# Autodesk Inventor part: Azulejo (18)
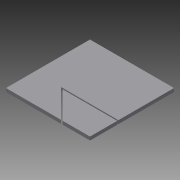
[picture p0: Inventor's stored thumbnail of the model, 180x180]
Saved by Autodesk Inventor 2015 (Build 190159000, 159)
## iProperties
Created: 2015-04
Part Number: Azulejo (18)
Material: Genérico
Document SubType Name: Modeling
Designer: Felipe
Density: 1 g/cm^3
Appearance: Padrão
Author: Felipe
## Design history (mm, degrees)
sketch "Sketch1"
  geometry: L1 (-1510, -7490)-(-1510, -6010); L2 (-3010, -1490)-(-3010, -10); L3 (-2990, 10)-(-1510, 10); L4 (-1510, -10)-(-2990, -10); L5 (-1510, -1490)-(-1510, -10); L6 (-10, 9010)-(-10, 10490); L7 (-1490, -10)-(-1490, -1490); L8 (-1490, -1490)-(-10, -1490); L9 (-10, -1510)-(-1490, -1510); L10 (-10, -2990)-(-10, -1510); L11 (-10, -5990)-(-10, -4510); L12 (-1490, -7490)-(-10, -7490); L13 (1490, 7510)-(1490, 8990); L14 (1490, 6010)-(1490, 7490); L15 (4490, -6010)-(3010, -6010); L16 (10, -1510)-(10, -2990); L17 (10, -3010)-(10, -4490); L18 (10, -4510)-(10, -5990); L19 (10, -5990)-(1490, -5990); L20 (1490, -6010)-(10, -6010); L21 (10, -7490)-(1490, -7490); L22 (2990, 9010)-(2990, 10490); L23 (1510, 8990)-(1510, 7510); L24 (1510, 7510)-(2990, 7510); L25 (2990, 7490)-(1510, 7490); L26 (1510, 7490)-(1510, 6010); L27 (1510, -5990)-(2990, -5990); L28 (2990, -6010)-(1510, -6010); L29 (1510, -7490)-(2990, -7490); L30 (3010, 10490)-(3010, 9010); L31 (3010, 9010)-(4490, 9010); L32 (4490, 8990)-(3010, 8990); L33 (4490, 7490)-(3010, 7490); L34 (4490, 1510)-(4490, 2990); L35 (4490, 10)-(4490, 1490); L36 (4490, -1490)-(4490, -10); L37 (4490, -2990)-(4490, -1510); L38 (3010, -5990)-(4490, -5990); L39 (3010, -7490)-(4490, -7490); L40 (4510, 9010)-(5990, 9010); L41 (5990, 8990)-(4510, 8990); L42 (4510, 7510)-(5990, 7510); L43 (5990, 7490)-(4510, 7490); L44 (4510, 3010)-(5990, 3010); L45 (5990, 2990)-(4510, 2990); L46 (4510, 2990)-(4510, 1510); L47 (4510, 1510)-(5990, 1510); L48 (5990, 1510)-(5990, 1740.185); L49 (5990, 1760.2)-(5990, 2259.8); L50 (5990, 2279.815)-(5990, 2990); L51 (5990, 1490)-(4510, 1490); L52 (4510, 1490)-(4510, 10); L53 (4510, 10)-(5990, 10); L54 (5990, 10)-(5990, 1490); L55 (5975.983, -10)-(4510, -10); L56 (4510, -10)-(4510, -1490); L57 (5990, -1510)-(5782.897, -1510); L58 (5782.897, -1510)-(5688.66, -1510); L59 (5668.66, -1510)-(5482.895, -1510); L60 (5482.895, -1510)-(5388.656, -1510); L61 (5368.656, -1510)-(4510, -1510); L62 (4510, -1510)-(4510, -2990); L63 (4510, -2990)-(5975.983, -2990); L64 (5990, -2975.728)-(5990, -2837.377)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; A1 r 250 centre (6000, 2010) between (5990, 2259.8) and (5990, 1760.2); A2 r 250 centre (6000, 2010) between (6010, 1760.2) and (6010, 2259.8); A3 r 270 centre (6000, 2010) between (5990, 2279.815) and (5990, 1740.185); A4 r 270 centre (6000, 2010) between (6010, 1740.185) and (6010, 2279.815); A5 r 3010.017 centre (0, 0) between (-1490, -2615.358) and (-346.554, -2990); A6 r 2990.017 centre (0, 0) between (-1490, -2592.316) and (-10, -2990); A7 r 3010.017 centre (0, 0) between (-2603.863, -1510) and (-1510, -2603.863); A8 r 2990.017 centre (0, 0) between (-2580.717, -1510) and (-1510, -2580.717); A9 r 3010.017 centre (0, 0) between (-2990, -346.554) and (-2615.358, -1490); A10 r 2990.017 centre (0, 0) between (-2990, -10) and (-2592.316, -1490); A11 r 2131.367 centre (7500, -1500) between (7490, 631.344) and (6010, 24.017); A12 r 2131.367 centre (7500, -1500) between (5975.983, -10) and (5368.656, -1490); A13 r 2131.367 centre (7500, -1500) between (5368.656, -1510) and (5975.983, -2990); A14 r 2131.367 centre (7500, -1500) between (6010, -3024.017) and (7190, -3608.703); A15 r 1831.367 centre (7500, -1500) between (7490.321, 331.342) and (6463.753, 10); A16 r 1831.367 centre (7500, -1500) between (6435.196, -10) and (6010, -435.196); A17 r 1831.367 centre (7500, -1500) between (5990, -463.753) and (5668.66, -1490); A18 r 1831.367 centre (7500, -1500) between (5668.66, -1510) and (5990, -2536.247); A19 r 1831.367 centre (7500, -1500) between (6010, -2564.804) and (6435.196, -2990); A20 r 1831.367 centre (7500, -1500) between (6463.753, -3010) and (7490, -3331.34); A21 r 2111.367 centre (7500, -1500) between (7490.047, 611.344) and (6024.272, 10); A22 r 2111.367 centre (7500, -1500) between (5990, -24.272) and (5388.656, -1490); A23 r 2111.367 centre (7500, -1500) between (5388.656, -1510) and (5990, -2975.728); A24 r 2111.367 centre (7500, -1500) between (6024.272, -3010) and (7210, -3591.357); A25 r 1811.367 centre (7500, -1500) between (7490.374, 311.342) and (6499.524, 10); A26 r 1811.367 centre (7500, -1500) between (6469.975, -10) and (6010, -469.975); A27 r 1811.367 centre (7500, -1500) between (5990, -499.524) and (5688.66, -1490); A28 r 1811.367 centre (7500, -1500) between (5688.66, -1510) and (5990, -2500.476); A29 r 1811.367 centre (7500, -1500) between (6010, -2530.025) and (6469.975, -2990); A30 r 1811.367 centre (7500, -1500) between (6499.524, -3010) and (7490, -3311.34); A31 r 449.871 centre (7499.449, -4060.672) between (7510, -4510.419) and (7521.546, -4510); 4 further points
  constraints: 954 end point, 64 point on circle, 31 centre point, 13 point on line, 1 horizontal, 1 other
extrude "Extrusion1" new body sketch "Sketch1" distance "d0" = 60; taper "d1" = 0 deg
extrude "Extrusion2" new body sketch "Sketch1" distance "d2" = 60; taper "d3" = 0 deg
body "Solid1"
body "Solid2"
